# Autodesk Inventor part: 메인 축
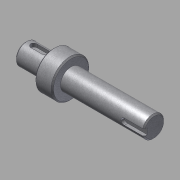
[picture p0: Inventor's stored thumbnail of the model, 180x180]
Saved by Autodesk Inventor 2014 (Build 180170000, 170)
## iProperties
Created: 2014-10
Part Number: 메인 축
Document SubType Name: Modeling
Designer: KYOUNG IL JANG
Density: 7.86 g/cm^3
Mass: 230.24 g
Surface Area: 74.3518 cm^2
Volume: 29.2926 cm^3
Material: 강철, 연강
Appearance: 금속-강(스테인리스, 브러시됨)
d0: 17.000 mm
d1: 30.000 mm
d2: 22.000 mm
d5: 17.000 mm
d6: 1.000 mm
d9: 5.000 mm
d10: 14.000 mm
d11: 4.000 mm
d12: 3.000 mm
d13: 0.00 deg
d14: 5.000 mm
d15: 18.000 mm
d16: 3.000 mm
d17: 0.00 deg
d19: 80.000 mm
d3: 65.997 mm
Author: SeoGD™ [www.esajin.kr]
Revision Number: 1
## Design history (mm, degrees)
sketch "스케치1"
  geometry: L1 (10.497, -57.5)-(112.497, -57.5); L2 (10.497, -66)-(32.497, -66); L3 (32.497, -72.5)-(46.5, -72.5); L4 (46.5, -66)-(112.497, -66); L5 (112.497, -66)-(112.497, -57.5); L6 (10.497, -66)-(10.497, -57.5); L7 (46.5, -69.749)-(46.5, -45.251) reference; L8 (46.5, -72.5)-(46.5, -66); L9 (32.497, -72.5)-(32.497, -66); L10 (32.497, -35)-(32.497, -80) reference; 3 further points
  constraints: 16 end point, 3 point on line, 2 parallel, 2 perpendicular, 1 collinear, 1 horizontal, 1 midpoint
  dimensions: "d0" = 17 diameter of L4 L1; "d1" = 30 diameter of L3 L1; "d2" = 22 distance of L2.start L2.end; "d3" = 65.99692 distance of L4.start L4.end (derived); "d5" = 17 diameter of L2 L1; "d19" = 80 distance between parallel lines of L5 L9
revolve "회전1" sketch "스케치1" stored, may be unused: angle "d4" = 90 deg
chamfer "모따기1" distance "d6" = 1; stored, may be unused: second distance "d7" = 2, angle "d8" = 45 deg
node "작업 평면1"
sketch "스케치2"
  geometry: L1 (-11, -7.5)-(-11, 7.5) reference; L2 (-4.5, 2.5)-(4.5, 2.5); L3 (4.5, -2.5)-(-4.5, -2.5); A1 r 2.5 centre (4.5, 0) between (4.5, -2.5) and (4.5, 2.5); A2 r 2.5 centre (-4.5, 0) between (-4.5, 2.5) and (-4.5, -2.5); 2 further points
  constraints: 4 end point, 4 point on circle, 4 tangent, 2 centre point, 1 horizontal alignment, 1 midpoint, 1 parallel, 1 perpendicular
  dimensions: "d9" = 5 distance between parallel lines of L3 L2; "d10" = 14 dimension on A1 A2; "d11" = 4 distance edge to line of A2 L1
extrude "돌출1" cut sketch "스케치2" distance "d12" = 3; taper "d13" = 0 deg
node "작업 평면2"
sketch "스케치3"
  geometry: L1 (32.998, 7.5)-(32.998, -7.5) reference; L2 (32.998, 2.5)-(17.498, 2.5); L3 (17.498, -2.5)-(32.998, -2.5); A1 r 2.5 centre (17.498, 0) between (17.498, 2.5) and (17.498, -2.5); 2 further points
  constraints: 4 end point, 2 perpendicular, 2 point on circle, 2 point on line, 2 tangent, 1 centre point, 1 horizontal alignment, 1 midpoint
  dimensions: "d14" = 5 distance between parallel lines of L3 L2; "d15" = 18 dimension on A1 L1
extrude "돌출2" cut sketch "스케치3" distance "d16" = 3; taper "d17" = 0 deg
node "솔리드1"
node "참조4"
node "참조5"
